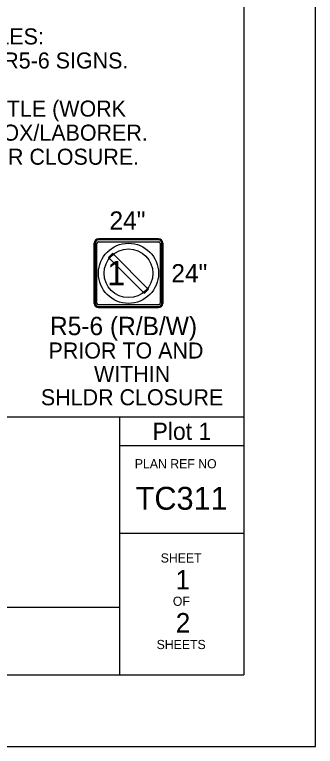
# Model space of a CAD drawing. Extents: x 99999.1 to 100055.7, y 99995 to 100013.2.
# Drawn here: x 100014.75 to 100016.062, y 99999.687 to 100002.881 of the extents above; entities that cross this region are included whole.
import ezdxf

# ---------------------------------------------------------------- set-up
doc = ezdxf.new("R2010")
doc.units = 0
for name, color, linetype in [('SH_GI_GeneralNotesBodyText', 7, 'Continuous'), ('SH_GI_PlotLimits', 7, 'Continuous'), ('SH_GI_SheetBorder', 7, 'Continuous'), ('SH_GI_SheetLocationText', 7, 'Continuous'), ('SH_GI_SheetTextInCells', 7, 'Continuous'), ('SH_GI_TitleBlockText', 7, 'Continuous'), ('TR_SN_ConstructionSigns', 7, 'Continuous')]:
    doc.layers.add(name, color=color, linetype=linetype)

msp = doc.modelspace()

# ---------------------------------------------------------------- linework, layer by layer
at = {"layer": 'SH_GI_PlotLimits'}
msp.add_lwpolyline([(99999.0625, 99999.6875), (100016.0625, 99999.6875), (100016.0625, 100010.6875), (99999.0625, 100010.6875)], close=True, dxfattribs=at)
at = {"layer": 'SH_GI_SheetBorder'}
for p, q in [((100015.75, 100010.375), (100015.75, 100000)), ((100000, 100001.1259), (100015.75, 100001.1259)), ((100015.2079, 100001.1259), (100015.2079, 100000)), ((100015.2079, 100001.0008), (100015.75, 100001.0008)), ((100015.2079, 100000.6176), (100015.75, 100000.6176)), ((100012.2055, 100000.2955), (100015.2079, 100000.2955)), ((100000, 100000), (100015.75, 100000))]:
    msp.add_line(p, q, dxfattribs=at)
at = {"layer": 'TR_SN_ConstructionSigns'}
for p, q in [((100015.3783, 100001.9019), (100015.1158, 100001.9019)), ((100015.1158, 100001.9019), (100015.3783, 100001.9019)), ((100015.3783, 100001.9019), (100015.1158, 100001.9019)), ((100015.3783, 100001.8972), (100015.1158, 100001.8972)), ((100015.0971, 100001.8831), (100015.0971, 100001.6206)), ((100015.0971, 100001.6206), (100015.0971, 100001.8831)), ((100015.0971, 100001.8831), (100015.0971, 100001.6206)), ((100015.1018, 100001.8831), (100015.1018, 100001.6206)), ((100015.1096, 100001.6206), (100015.1096, 100001.8831)), ((100015.1158, 100001.8894), (100015.3783, 100001.8894)), ((100015.3846, 100001.8831), (100015.3846, 100001.6206)), ((100015.3924, 100001.6206), (100015.3924, 100001.8831)), ((100015.3971, 100001.6206), (100015.3971, 100001.8831)), ((100015.3971, 100001.8831), (100015.3971, 100001.6206)), ((100015.3971, 100001.6206), (100015.3971, 100001.8831)), ((100015.3783, 100001.6144), (100015.1158, 100001.6144)), ((100015.1158, 100001.6066), (100015.3783, 100001.6066)), ((100015.1158, 100001.6019), (100015.3783, 100001.6019)), ((100015.3783, 100001.6019), (100015.1158, 100001.6019)), ((100015.1158, 100001.6019), (100015.3783, 100001.6019))]:
    msp.add_line(p, q, dxfattribs=at)
msp.add_lwpolyline([(100015.3305, 100001.6861), (100015.1813, 100001.8353), (100015.1778, 100001.8389), (100015.1601, 100001.8212), (100015.3128, 100001.6685), (100015.3164, 100001.6649), (100015.3341, 100001.6826), (100015.3305, 100001.6861)], dxfattribs=at)
for radius in [0.1313, 0.1062]:
    msp.add_circle((100015.2471, 100001.7519), radius, dxfattribs=at)
for centre, radius, start, end in [((100015.1158, 100001.8831), 0.0187, 90, 180), ((100015.1158, 100001.8831), 0.0187, 90, 180), ((100015.1158, 100001.8831), 0.0187, 90, 180), ((100015.1158, 100001.8831), 0.0141, 90, 180), ((100015.3783, 100001.8831), 0.0187, 0, 90), ((100015.3783, 100001.8831), 0.0187, 0, 90), ((100015.3783, 100001.8831), 0.0187, 0, 90), ((100015.3783, 100001.8831), 0.0141, 0, 90), ((100015.1158, 100001.8831), 0.00625, 90, 180), ((100015.3783, 100001.8831), 0.00625, 0, 90), ((100015.1158, 100001.6206), 0.0187, 180, 270), ((100015.1158, 100001.6206), 0.0187, 180, 270), ((100015.1158, 100001.6206), 0.0187, 180, 270), ((100015.1158, 100001.6206), 0.0141, 180, 270), ((100015.1158, 100001.6206), 0.00625, 180, 270), ((100015.3783, 100001.6206), 0.0141, 270, 0), ((100015.3783, 100001.6206), 0.00625, 270, 0), ((100015.3783, 100001.6206), 0.0187, 270, 0), ((100015.3783, 100001.6206), 0.0187, 270, 0), ((100015.3783, 100001.6206), 0.0187, 270, 0)]:
    msp.add_arc(centre, radius, start, end, dxfattribs=at)

# ---------------------------------------------------------------- texts
at = {"layer": 'SH_GI_GeneralNotesBodyText'}
for s, p in [('8. BICYCLIST ACCOMMODATIONS, WHERE FACILITY OPEN TO BICYCLES:', (100011.549, 100002.7506)), ('(A) BICYCLES PROHIBITED VIA R5-601 (IF EXIT-RAMP PRESENT) & R5-6 SIGNS. ', (100011.689, 100002.6456)), ('(B) BICYCLES PROHIBITED VIA R5-6 SIGN(S). PROVIDE FREE SHUTTLE (WORK ', (100011.689, 100002.4356)), ('TRUCK, VAN, OR BUS OK) + CONTACT INFORMATION/PHONE BOX/LABORER. ', (100011.839, 100002.3306)), ('(C) STOP WORK OPS. & ESCORT BICYCLISTS THROUGH SHOULDER CLOSURE.', (100011.689, 100002.2256))]:
    msp.add_text(s, height=0.07, rotation=360, dxfattribs=at).set_placement(p)
at = {"layer": 'SH_GI_SheetBorder'}
msp.add_text('PLAN REF NO', height=0.040032, dxfattribs=at).set_placement((100015.2747, 100000.9008))
at = {"layer": 'SH_GI_SheetLocationText'}
msp.add_text('Plot 1', height=0.075, dxfattribs=at).set_placement((100015.3518, 100001.025))
at = {"layer": 'SH_GI_SheetTextInCells'}
for s, p in [('SHEET', (100015.3877, 100000.4896)), ('OF', (100015.4406, 100000.3008)), ('SHEETS', (100015.3698, 100000.112))]:
    msp.add_text(s, height=0.04003, dxfattribs=at).set_placement(p)
at = {"layer": 'SH_GI_TitleBlockText'}
for s, height, p in [('TC311', 0.1, (100015.2784, 100000.72)), ('1', 0.085, (100015.4526, 100000.3723)), ('2', 0.085, (100015.4534, 100000.1843))]:
    msp.add_text(s, height=height, dxfattribs=at).set_placement(p)
at = {"layer": 'TR_SN_ConstructionSigns'}
for s, height, p in [('24"', 0.08, (100015.164, 100001.9419)), ('24"', 0.08, (100015.434, 100001.7119)), ('R5-6 (R/B/W)', 0.08, (100014.9045, 100001.4819)), ('PRIOR TO AND', 0.07, (100014.898, 100001.3799)), ('WITHIN', 0.07, (100015.0965, 100001.2779)), ('SHLDR CLOSURE', 0.07, (100014.8647, 100001.1759))]:
    msp.add_text(s, height=height, rotation=360, dxfattribs=at).set_placement(p)
msp.add_text('1', height=0.1065, dxfattribs=at).set_placement((100015.1538, 100001.6994))

doc.saveas('drawing.dxf')
